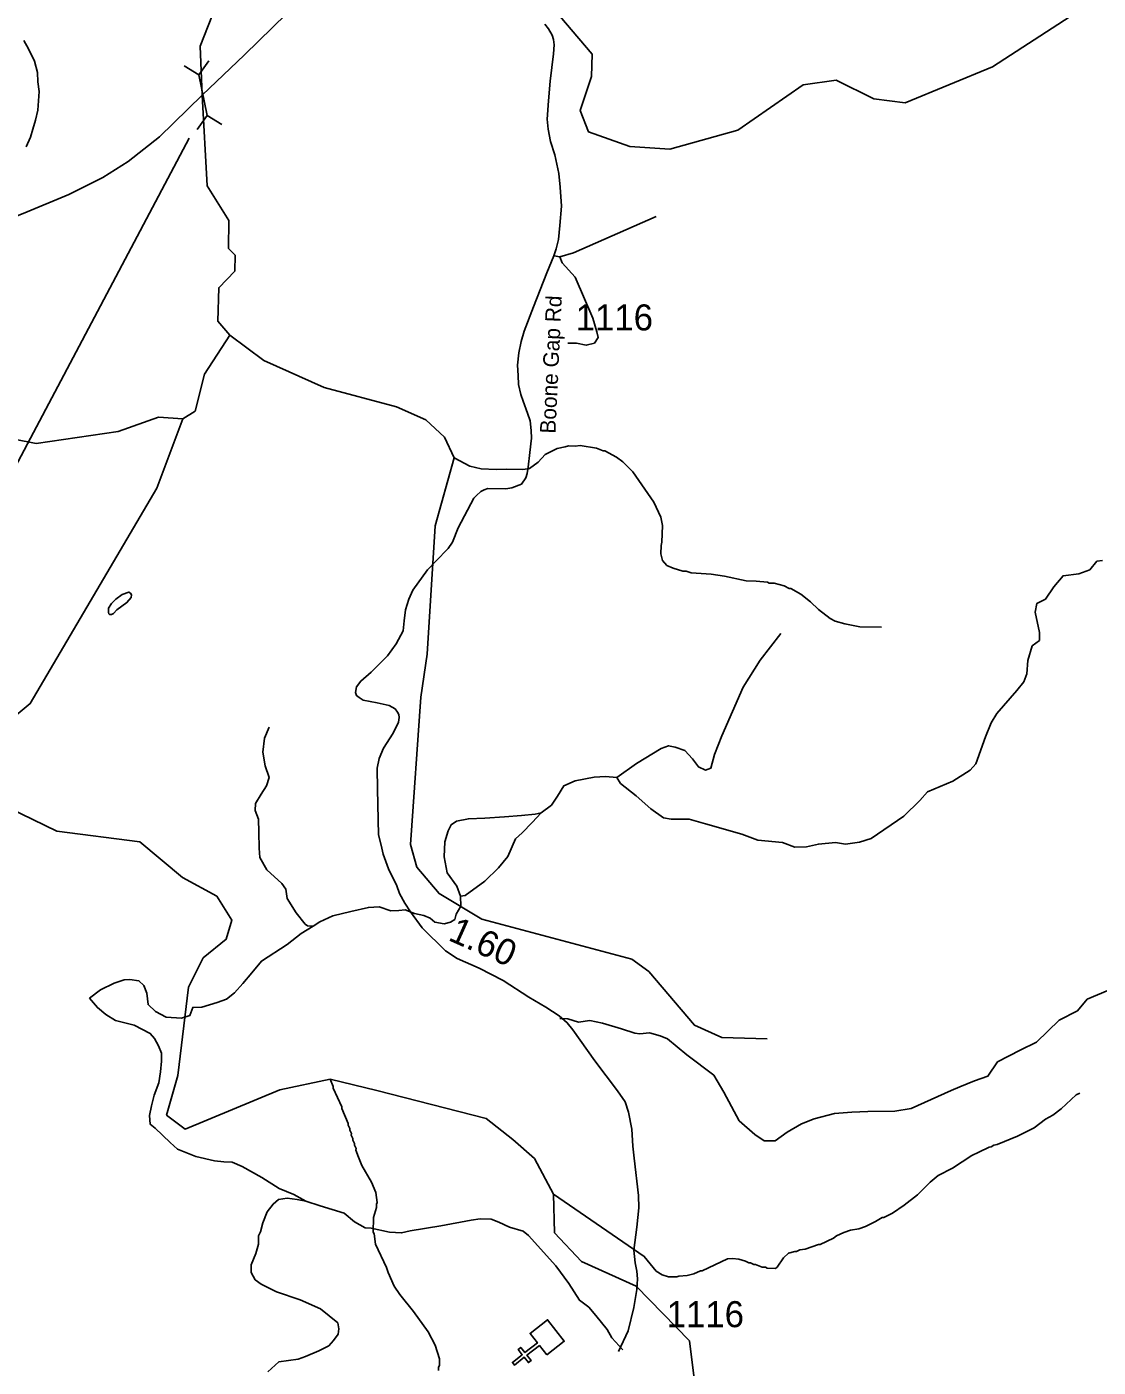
# Model space of a CAD drawing. Extents: x 1248224 to 1454986, y 825081 to 985870.
# Drawn here: x 1328657 to 1333804, y 840892 to 847331 of the extents above; entities that cross this region are included whole.
import ezdxf

# ---------------------------------------------------------------- set-up
doc = ezdxf.new("R2010")
doc.units = 0
for name, color, linetype in [('Exist Cultural Church CELL', 7, 'Continuous'), ('Exist Hydrographic Creek Single Shore', 7, 'Continuous'), ('Exist Hydrographic Misc Water Feature', 7, 'Continuous'), ('Exist Road Non-System Type 51', 7, 'Continuous'), ('Exist Road Primary NC Attributed', 7, 'Continuous'), ('Exist Road Primary NC Structure Culvert CELL', 7, 'Continuous'), ('Exist Road Primary NC Structure Culvert Number Label', 7, 'Continuous'), ('Exist Road Secondary Mileage Hundredths English Label', 7, 'Continuous'), ('Exist Road Secondary Type 51 Attributed', 7, 'Continuous'), ('Exist Road Secondary Type 51 Label', 7, 'Continuous'), ('Exist Road Secondary Type 51 Number Label', 7, 'Continuous')]:
    doc.layers.add(name, color=color, linetype=linetype)

msp = doc.modelspace()

# ---------------------------------------------------------------- linework, layer by layer
at = {"layer": 'Exist Cultural Church CELL'}
msp.add_lwpolyline([(1331154.8, 840951.6), (1331119.8, 840996.4), (1331059.7, 840949.6), (1331079.3, 840924.4), (1331066.7, 840914.6), (1331047.1, 840939.8), (1330999.6, 840902.9), (1330989.8, 840915.5), (1331037.2, 840952.5), (1331017.6, 840977.7), (1331030.2, 840987.5), (1331049.8, 840962.3), (1331109.9, 841009.1), (1331074.6, 841054.6), (1331158.6, 841120), (1331238.8, 841016.9)], close=True, dxfattribs=at)
at = {"layer": 'Exist Hydrographic Creek Single Shore'}
for points in [[(1329632.1, 845849.7), (1329575.1, 845916.4), (1329579.1, 846077.2), (1329656.1, 846157.7), (1329657.2, 846233.2), (1329625.2, 846266.7), (1329628.1, 846401.2), (1329523.2, 846567.4), (1329499.8, 847001.9), (1329489.1, 847237.8), (1329622.1, 847576.6), (1329708.1, 847689.7), (1329790.1, 847970.4), (1329868.1, 848136.3), (1329871.1, 848221.6), (1329838.1, 848278), (1329740.1, 848365.4), (1329726.1, 848480.6), (1329639.1, 848643.2), (1329634.1, 848800.8), (1329602.1, 848850.7), (1329638.1, 848974.7)], [(1329406.2, 845447.1), (1329465.1, 845485.4), (1329511.2, 845661.7), (1329632.1, 845849.7)]]:
    msp.add_lwpolyline(points, dxfattribs=at)
at = {"layer": 'Exist Hydrographic Misc Water Feature'}
for points in [[(1335004.2, 846634.6), (1334249.2, 847191.4), (1334162.2, 847377), (1334088.9, 847458.2), (1333930.1, 847440.8), (1333670.1, 847380.3), (1333297.1, 847138.3), (1332876.2, 846966.2), (1332727.2, 846985.6), (1332545.2, 847074.7), (1332387.1, 847051.6), (1332073.2, 846834.7), (1331746.1, 846742.7), (1331554.2, 846756.4), (1331356.1, 846826.1), (1331316.1, 846928.6), (1331370.2, 847091.7), (1331373.1, 847200), (1331153.1, 847457.1), (1331065.1, 847610), (1331028.1, 847784.7), (1330858.1, 848014.6), (1330792.1, 848058.6), (1330750.1, 848085)], [(1332213.2, 842469), (1331996.2, 842476.6), (1331864.2, 842535.2), (1331645.2, 842792.4), (1331563.2, 842853.1), (1330842.2, 843044.8), (1330637.2, 843167.1), (1330531.2, 843294), (1330500.2, 843402.9), (1330550.2, 844111), (1330580.2, 844317.2), (1330619.2, 844933.6), (1330709.5, 845260.6), (1330663.1, 845359.5), (1330573.1, 845443.3), (1330433.2, 845505.3), (1330085.1, 845597.6), (1329796.2, 845728.1), (1329632.1, 845849.7)], [(1326420.1, 844006.8), (1326356.1, 844116.5), (1326261.6, 844688.2), (1326335.1, 845009.8), (1326392.1, 845291), (1326569.1, 845386), (1327091.1, 845592.1), (1327441.1, 845591.6), (1328070.2, 845401.7), (1328180.2, 845432.4), (1328702.1, 845329.9), (1329096.1, 845387.7), (1329289.1, 845456), (1329406.2, 845447.1)], [(1328444.2, 843890.7), (1328673.1, 844079.8), (1329281.1, 845114.8), (1329406.2, 845447.1)], [(1332763.3, 844446.5), (1332659.4, 844449), (1332587.7, 844462.6), (1332540, 844475.7), (1332516.3, 844488.3), (1332461.2, 844531.6), (1332422.1, 844568.5), (1332374.9, 844605.6), (1332327.6, 844632.7), (1332319.6, 844632.9), (1332295.8, 844645.5), (1332248.1, 844658.5), (1332224.1, 844659.1), (1332216.2, 844663.3), (1332160.3, 844668.6), (1332112.3, 844669.8), (1332008.8, 844692.2), (1331945, 844701.7), (1331849.2, 844707.9), (1331825.4, 844716.5), (1331809.4, 844716.8), (1331761.7, 844729.9), (1331732, 844742.7), (1331710.6, 844767.2), (1331703.3, 844799.3), (1331704.1, 844839.3), (1331708.5, 844855.2), (1331710.3, 844935.1), (1331706.9, 844959.2), (1331703.2, 844975.3), (1331668.8, 845048.1), (1331568.1, 845192.4), (1331536.9, 845225.1), (1331521.2, 845241.5), (1331489.7, 845264.3), (1331434.3, 845293.5), (1331426.3, 845293.7), (1331394.7, 845306.5), (1331315, 845320.3), (1331290.9, 845316.9), (1331258.9, 845317.6), (1331242.8, 845314), (1331204.6, 845304.9), (1331172.3, 845289.7), (1331148, 845276.3), (1331113.1, 845239.1), (1331072.4, 845210), (1331040.3, 845204.8), (1330960.4, 845206.6), (1330912.3, 845203.8), (1330840.4, 845207.5), (1330784.6, 845220.8), (1330709.5, 845260.6)], [(1329084.6, 844581.6), (1329114.6, 844604), (1329146.9, 844615.3), (1329154.8, 844611.1), (1329160.5, 844603), (1329158.3, 844589), (1329137.8, 844565.5), (1329089, 844530.7), (1329072.6, 844513.1), (1329064.4, 844507.3), (1329056.4, 844507.4), (1329050.5, 844511.6), (1329048.7, 844517.6), (1329049.1, 844537.6), (1329063.6, 844561.2), (1329084.6, 844581.6)], [(1331321.6, 841400.2), (1331191.7, 841538.5), (1331186.7, 841723.5), (1331095.9, 841894.3), (1330992.7, 841986), (1330864.4, 842087.6), (1330339.2, 842221.1), (1330114.4, 842275.6), (1329873.2, 842223.9), (1329418.2, 842036.1), (1329328.2, 842103.6), (1329382.2, 842292.8), (1329434.2, 842718.6), (1329504.2, 842858.3), (1329614.2, 842948), (1329641.2, 843039.4), (1329569.2, 843155.7), (1329404.1, 843244.4), (1329200.2, 843415.9), (1328801.2, 843466.6), (1328570.2, 843579.6)], [(1330634.3, 840877.1), (1330634.7, 840893.1), (1330638.9, 840901), (1330639.7, 840932.9), (1330619.1, 840997.4), (1330584.5, 841062.2), (1330514.8, 841159.8), (1330448.6, 841241.3), (1330421.5, 841282), (1330393, 841346.6), (1330385.5, 841370.8), (1330332.1, 841484), (1330325.1, 841532.2), (1330321.3, 841540.3), (1330323, 841612.2), (1330336.1, 841659.9), (1330336.4, 841675.9), (1330340.6, 841683.8), (1330333.7, 841732), (1330312.8, 841780.4), (1330266.6, 841861.5), (1330249.6, 841901.9), (1330238.3, 841934.2), (1330238.5, 841942.2), (1330230.8, 841958.3), (1330231, 841966.3), (1330223.3, 841982.5), (1330223.5, 841990.5), (1330215.9, 842006.7), (1330216, 842014.6), (1330208.4, 842030.8), (1330208.6, 842038.8), (1330201, 842055), (1330201.2, 842063), (1330170.8, 842135.7), (1330171, 842143.7), (1330129, 842232.7), (1330129.2, 842240.7), (1330114.4, 842275.6)], [(1333716.8, 842208.5), (1333698.6, 842200.9), (1333627.1, 842132.7), (1333586.4, 842103.6), (1333551.9, 842084.4), (1333497, 842041.7), (1333416.1, 842001.6), (1333319.2, 841961.9), (1333303.1, 841958.3), (1333290.9, 841950.6), (1333280.8, 841948.8), (1333230.3, 841926), (1333197.9, 841908.7), (1333104.6, 841849), (1333035.7, 841812.6), (1332997, 841781.5), (1332935.6, 841720.9), (1332872.5, 841670.4), (1332815.6, 841631.8), (1332775.2, 841610.7), (1332767.2, 841610.9), (1332734.7, 841591.7), (1332686.2, 841568.8), (1332653.9, 841557.6), (1332613.8, 841550.5), (1332581.5, 841539.3), (1332547.2, 841524.1), (1332532.9, 841512.4), (1332468.2, 841481.9), (1332460.2, 841482.1), (1332395.7, 841459.6), (1332371.6, 841456.2), (1332355.4, 841448.6), (1332347.4, 841448.8), (1332317.2, 841439.5), (1332292.7, 841418), (1332261.7, 841372.8), (1332253.6, 841367), (1332213.6, 841367.9), (1332205.6, 841372.1), (1332189.7, 841372.5), (1332158, 841385.2), (1332150, 841385.4), (1332134.2, 841393.8), (1332126.2, 841394), (1332110.4, 841402.4), (1332078.5, 841411.1), (1332046.6, 841413.8), (1332022.6, 841412.4), (1331901.2, 841355.3), (1331893.3, 841355.5), (1331861, 841340.2), (1331828.8, 841333), (1331788.7, 841329.9), (1331780.6, 841326.1), (1331740.6, 841327), (1331708.8, 841335.8), (1331681.2, 841354.4), (1331623.5, 841424.1), (1331186.7, 841723.5)], [(1331186, 838082.3), (1331242.3, 838030.5), (1331386.8, 838020.3), (1331493.3, 838035.4), (1331645.2, 838130.8), (1331809.8, 838373.6), (1331777.3, 839503.6), (1331986.2, 839890.1), (1332066.8, 839944.8), (1331990.2, 840073.8), (1331818.3, 840543.4), (1331872.9, 840761.9), (1331841.3, 841018.6), (1331584.8, 841281.9), (1331321.6, 841400.2)]]:
    msp.add_lwpolyline(points, dxfattribs=at)
at = {"layer": 'Exist Road Non-System Type 51'}
for points in [[(1331190.6, 846231.4), (1331217, 846226.2), (1331283.3, 846245.8), (1331681.1, 846420.3)], [(1331217, 846226.2), (1331229.3, 846196.7), (1331290.7, 846127.9), (1331376.6, 845931.3), (1331396.2, 845864.9), (1331401.2, 845837.9), (1331384, 845810.9), (1331344.7, 845801), (1331298, 845810.9), (1331256.3, 845810.9)], [(1331490.8, 843725.6), (1331509.6, 843696.7), (1331584.3, 843637.2), (1331655.3, 843573.9), (1331716.6, 843531.7), (1331753, 843524.1), (1331839.2, 843524.1), (1331917.8, 843503), (1332092.2, 843453.1), (1332168.9, 843424.3), (1332287.7, 843412.8), (1332347.1, 843389.8), (1332402.7, 843391.7), (1332460.2, 843405.1), (1332542.6, 843412.8), (1332590.5, 843405.1), (1332657.5, 843414.7), (1332713.1, 843432), (1332870.3, 843539.4), (1332947.5, 843614.1), (1332983.9, 843656.3), (1333106.6, 843708.1), (1333189, 843759.9), (1333215.8, 843790.6), (1333263.7, 843921), (1333290.5, 843988.1), (1333317.4, 844032.2), (1333413.2, 844143.4), (1333447.4, 844184.2), (1333460.9, 844222.5), (1333466.6, 844287.7), (1333487.7, 844356.8), (1333522.2, 844383.6), (1333522.2, 844422), (1333501.1, 844519.8), (1333508.8, 844560.1), (1333550.9, 844581.1), (1333591.2, 844640.6), (1333635.3, 844694.3), (1333711.9, 844703.9), (1333763.7, 844723.1), (1333798.2, 844763.3), (1333825, 844767.2)], [(1331490.8, 843725.6), (1331586.6, 843792.8), (1331705.4, 843863.7), (1331739.9, 843877.1), (1331772.5, 843871.4), (1331818.5, 843854.1), (1331854.9, 843813.9), (1331883.7, 843775.5), (1331918.1, 843760.2), (1331943.1, 843769.7), (1331960.3, 843835), (1331996.7, 843925.1), (1332097.9, 844158.1), (1332180.3, 844288.5), (1332279.9, 844417)], [(1330474.9, 843089.5), (1330444, 843085.7), (1330405.6, 843083.8), (1330350.1, 843102.9), (1330298.3, 843101), (1330214, 843081.8), (1330127.8, 843060.7), (1330064.5, 843032), (1330031.9, 843010.9), (1330005.1, 843012.8), (1329993.6, 843020.5), (1329951.5, 843074.2), (1329907.4, 843143.2), (1329901.6, 843189.2), (1329882.5, 843216.1), (1329809.6, 843281.3), (1329777.1, 843340.7), (1329773.2, 843384.8), (1329771.3, 843461.6), (1329769.4, 843524.9), (1329754.1, 843567), (1329756.1, 843600), (1329782.9, 843644.1), (1329807.8, 843684.4), (1329821.2, 843724.7), (1329802.1, 843780.3), (1329790.6, 843847.4), (1329798.2, 843914.6), (1329821.2, 843966.3)], [(1331127.4, 843555.2), (1331177.3, 843591.7), (1331206, 843635.8), (1331236.7, 843685.7), (1331292.2, 843708.7), (1331382.3, 843725.9), (1331437.1, 843729.5), (1331490.8, 843725.6)], [(1330474.9, 843089.5), (1330519.9, 843072), (1330564, 843062.4), (1330594.7, 843048.9), (1330617.7, 843029.8), (1330661.7, 843022.1), (1330692.4, 843029.8), (1330713.5, 843043.2), (1330719.2, 843068.1), (1330742.2, 843106.5), (1330740.3, 843154.4), (1330723.1, 843202.4), (1330677.1, 843267.6), (1330661.7, 843344.3), (1330665.6, 843415.2), (1330680.9, 843468.9), (1330696.2, 843497.7), (1330721.1, 843515), (1330778.6, 843526.5), (1330857.2, 843530.3), (1330951.1, 843536.1), (1331033.5, 843541.8), (1331098.7, 843549.5), (1331127.4, 843555.2)], [(1331127.4, 843555.2), (1331085.3, 843509.2), (1331037.4, 843459.3), (1331004.8, 843430.6), (1330968.4, 843346.2), (1330922.4, 843290.6), (1330857.2, 843227.3), (1330763.3, 843158.3), (1330740.3, 843154.4)], [(1328957.9, 842664.2), (1329011.2, 842704.8), (1329076.4, 842737.4), (1329124.3, 842752.7), (1329151.1, 842754.6), (1329195.2, 842748.9), (1329218.2, 842725.9), (1329233.5, 842689.4), (1329239.3, 842633.8), (1329275.7, 842601.2), (1329325.5, 842574.4), (1329400.3, 842568.6), (1329440.5, 842582), (1329453.9, 842620.4), (1329498, 842622.3), (1329570.8, 842643.4), (1329616.8, 842660.7), (1329655.2, 842691.4), (1329695.4, 842735.5), (1329737.6, 842787.2), (1329783.6, 842842.9), (1329908.1, 842923.4), (1329975.2, 842975.2), (1330031.9, 843010.9)], [(1331217.6, 842567), (1331256.1, 842565.1), (1331307.6, 842550.4), (1331361.7, 842557.7), (1331423.1, 842545.5), (1331513.9, 842518.4), (1331577.8, 842496.3), (1331602.3, 842493.9), (1331649, 842498.8), (1331700.5, 842484), (1331734.9, 842469.3), (1331828.2, 842393.1), (1331958.4, 842294.8), (1332005, 842213.7), (1332078.7, 842076.1), (1332154.8, 842009.7), (1332199, 841980.3), (1332253.1, 841980.3), (1332309.5, 842022), (1332378.3, 842061.3), (1332439.7, 842085.9), (1332537.9, 842110.5), (1332621.4, 842117.9), (1332697.5, 842120.3), (1332827.7, 842122.8), (1332906.3, 842135.1), (1333097.8, 842221.1), (1333139.5, 842238.3), (1333210.7, 842267.8), (1333274.6, 842289.9), (1333321.3, 842358.7), (1333429.3, 842415.2), (1333508.7, 842454.3), (1333616.7, 842559.9), (1333705.1, 842604.2), (1333751.8, 842660.7), (1333850, 842702.5)], [(1329996.9, 841690.5), (1329939.4, 841721.9), (1329868.8, 841750.7), (1329786.4, 841803), (1329691, 841856.7), (1329642.6, 841877.6), (1329603.4, 841878.9), (1329558.9, 841884.1), (1329468.7, 841905.1), (1329381.1, 841939.1), (1329345.8, 841971.8), (1329273.9, 842041.2), (1329249.5, 842059.7), (1329246.9, 842101.6), (1329256, 842147.4), (1329269.1, 842198.4), (1329291.3, 842258.6), (1329299.2, 842310.9), (1329303.1, 842361.9), (1329303.1, 842401.2), (1329288.7, 842436.5), (1329270.4, 842471.9), (1329249.5, 842495.4), (1329172.3, 842534.7), (1329082.1, 842558.2), (1329036.4, 842587), (1328995.8, 842619.7), (1328957.9, 842664.2)], [(1329996.9, 841690.5), (1329954.9, 841697.1), (1329907.8, 841703.6), (1329866, 841698.4), (1329839.8, 841676.1), (1329811, 841638.2), (1329790.1, 841585.8), (1329779.7, 841542.7), (1329769.2, 841523), (1329770.5, 841483.8), (1329757.4, 841438), (1329733.9, 841384.3), (1329735.2, 841347.7), (1329753.5, 841312.4), (1329782.3, 841291.4), (1329856.8, 841254.8), (1329970.6, 841215.5), (1330068.6, 841172.4), (1330150.6, 841105), (1330155.9, 841076.3), (1330153.3, 841051.4), (1330131, 841020), (1330107.5, 840995.1), (1330060.4, 840970.3), (1329996.4, 840944.1), (1329961.1, 840931), (1329868.2, 840917.9), (1329814.6, 840870.8)], [(1331520.5, 840975.5), (1331468, 841033.2), (1331444.5, 841073.7), (1331390.9, 841140.5), (1331356.9, 841181), (1331312.4, 841213.7), (1331261.5, 841293.6), (1331198.7, 841378.6), (1331066.6, 841525.2), (1331042.1, 841545.3), (1330975.4, 841565), (1330924.4, 841588.5), (1330887.8, 841602.9), (1330835.5, 841605.5), (1330792.4, 841599), (1330645.9, 841571.5), (1330498.2, 841546.6), (1330457.6, 841537.5), (1330400.1, 841541.4), (1330311.2, 841559.7), (1330282.4, 841561), (1330231.4, 841591.1), (1330181.7, 841633), (1330066.2, 841668.2), (1329996.9, 841690.5)]]:
    msp.add_lwpolyline(points, dxfattribs=at)
at = {"layer": 'Exist Road Primary NC Attributed'}
msp.add_lwpolyline([(1328395, 846338.9), (1328638.7, 846433.7), (1328858.3, 846525.8), (1329021.5, 846606.6), (1329144.2, 846684.2), (1329293.7, 846802.4), (1329499.8, 847001.9), (1329703.2, 847195.6), (1329904.6, 847392.4), (1330224.8, 847710.2), (1330603.5, 848074.9)], dxfattribs=at)
at = {"layer": 'Exist Road Primary NC Structure Culvert CELL'}
for p, q in [((1329412.9, 847143.4), (1329483.6, 847099.4)), ((1329531.4, 847167.6), (1329483.6, 847099.4)), ((1329523.3, 846905), (1329483.6, 847099.4)), ((1329475.6, 846836.8), (1329523.3, 846905)), ((1329594, 846861), (1329523.3, 846905))]:
    msp.add_line(p, q, dxfattribs=at)
at = {"layer": 'Exist Road Primary NC Structure Culvert Number Label'}
msp.add_line((1329437.4, 846795.6), (1327423.4, 842995.4), dxfattribs=at)
at = {"layer": 'Exist Road Secondary Type 51 Attributed'}
for points in [[(1331146, 847343.9), (1331163, 847321.2), (1331180.2, 847291.3), (1331187.5, 847270), (1331190.2, 847243.6), (1331187.9, 847201.4), (1331171.8, 847069), (1331162.5, 846975.5), (1331156.6, 846887.9), (1331161.4, 846839.4), (1331173.6, 846780.4), (1331193.6, 846715.5), (1331213.6, 846627), (1331219, 846559.9), (1331226, 846468.7), (1331218.3, 846376.1), (1331210.8, 846308.5), (1331200, 846264.9), (1331188.2, 846230), (1331154.8, 846148.8), (1331092, 845985.9), (1331046.8, 845868.4), (1331031.9, 845819.8), (1331021, 845764.5), (1331014.6, 845705), (1331016.9, 845656), (1331019.8, 845612.5), (1331030.7, 845564.8), (1331041.8, 845532.2), (1331061.8, 845475.4), (1331074.9, 845438.5), (1331079.5, 845391.5), (1331081.8, 845355.2), (1331073.6, 845286.7), (1331066.3, 845215), (1331060.9, 845185), (1331053.8, 845164.3), (1331032.8, 845133.3), (1330987.1, 845115.8), (1330957.8, 845111.1), (1330872.1, 845113.4), (1330854.9, 845106.1), (1330837.7, 845098.8), (1330817.7, 845078.9), (1330804.4, 845066.6), (1330729.7, 844923.7), (1330702.4, 844855.6), (1330680.7, 844825.7), (1330622.6, 844764), (1330582.4, 844722.8), (1330511.4, 844625.1), (1330491.5, 844581.6), (1330476.9, 844530.8), (1330469.7, 844478.1), (1330464.2, 844429.1), (1330431.7, 844367.4), (1330389.5, 844310), (1330311.1, 844230.3), (1330261.4, 844187.7), (1330241.4, 844160.5), (1330235.5, 844133.3), (1330241, 844118.8), (1330252.8, 844108.8), (1330272.8, 844096.1), (1330340.8, 844083.4), (1330398, 844070.7), (1330426.1, 844054.3), (1330438.4, 844038.9), (1330444.3, 844027.6), (1330445.2, 844013.5), (1330442.9, 843991.3), (1330416.4, 843938.5), (1330370.8, 843866.5), (1330349, 843816.6), (1330340.4, 843770.3), (1330342.2, 843668.7), (1330347.2, 843450), (1330359, 843400), (1330368.9, 843357.4), (1330394.4, 843286.6), (1330435.1, 843204.4), (1330446.8, 843168), (1330472.8, 843121.5), (1330500.1, 843079.7), (1330555.7, 843002.8), (1330667.7, 842892.2), (1330723.9, 842855.8), (1330829.9, 842808.4), (1330945.2, 842749.2), (1331069.1, 842669.5), (1331150.7, 842622.3), (1331215.2, 842579.7), (1331253.3, 842547), (1331280.5, 842512.5), (1331385.3, 842364.6), (1331495.1, 842219.4), (1331532.3, 842166.8), (1331548.2, 842117.8), (1331563.6, 842036.1), (1331568.2, 841953.5), (1331575.4, 841896.4), (1331595.4, 841716.7), (1331597.7, 841657.7), (1331587.7, 841565.1), (1331572.7, 841454.4), (1331580, 841393.6), (1331587.2, 841353.7), (1331590.9, 841317.4), (1331588.1, 841264.8), (1331572.7, 841179.5), (1331545.5, 841066.9), (1331500.1, 840967.1)], [(1328653.4, 846754.2), (1328674.8, 846801.1), (1328685.1, 846839.1), (1328699, 846882.5), (1328709, 846930.6), (1328716.7, 847019.5), (1328710.3, 847065.9), (1328708.5, 847111.2), (1328694, 847166.5), (1328664.5, 847224.6), (1328641.8, 847264.5)]]:
    msp.add_lwpolyline(points, dxfattribs=at)

# ---------------------------------------------------------------- texts
at = {"layer": 'Exist Road Secondary Mileage Hundredths English Label'}
msp.add_text('1.60', height=125, rotation=335.89776, dxfattribs=at).set_placement((1330676.1, 842945.7))
at = {"layer": 'Exist Road Secondary Type 51 Label'}
msp.add_text('Boone Gap Rd', height=75, rotation=87.32918, dxfattribs=at).set_placement((1331196.7, 845375.6))
at = {"layer": 'Exist Road Secondary Type 51 Number Label'}
for p in [(1331293.5, 845872.5), (1331730.7, 841084.6)]:
    msp.add_text('1116', height=125, dxfattribs=at).set_placement(p)

doc.saveas('drawing.dxf')
